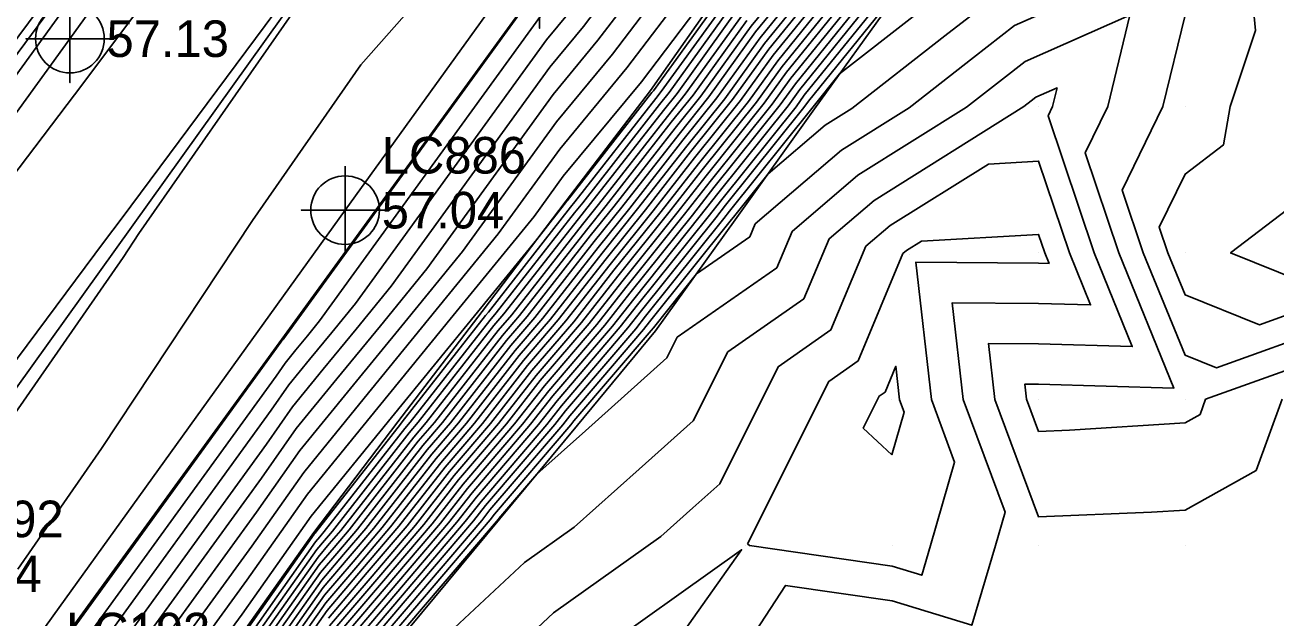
# Model space of a CAD drawing. Extents: x 2188792 to 2191981, y 386090 to 389710.
# Drawn here: x 2190090.9 to 2190176.3, y 387535.2 to 387575.7 of the extents above; entities that cross this region are included whole.
import ezdxf

# ---------------------------------------------------------------- set-up
doc = ezdxf.new("R2010")
doc.units = 0
for name, color, linetype in [('DTM Contours Major', 7, 'Continuous'), ('DTM Contours Minor', 7, 'Continuous'), ('Exist DTM Breakline', 7, 'Continuous'), ('Exist DTM QL2 LIDAR Elevation Point', 7, 'Continuous'), ('Exist Roads EOP', 7, 'Continuous'), ('Exist Roads EOP Cogo Number', 7, 'Continuous'), ('Exist Roads EOP Cogo Point CELL', 7, 'Continuous'), ('Exist Roads EOT', 7, 'Continuous'), ('Exist Roads EOT Cogo Elevation', 7, 'Continuous'), ('Exist Roads EOT Cogo Number', 7, 'Continuous'), ('Exist Roads EOT Cogo Point CELL', 7, 'Continuous'), ('PH Exist DTM Breakline', 7, 'Continuous')]:
    doc.layers.add(name, color=color, linetype=linetype)

msp = doc.modelspace()

# ---------------------------------------------------------------- linework, layer by layer
at = {"layer": 'DTM Contours Major'}
for points in [[(2190151.311, 387661.898), (2190146.496, 387654.704), (2190134.166, 387637.26), (2190130.399, 387632.051), (2190120.729, 387617.824), (2190106.225, 387596.486), (2190103.722, 387593.114), (2190101.482, 387589.813), (2190086.86, 387570.121)], [(2190091.393, 387530.607), (2190108.388, 387554.062), (2190108.431, 387554.123), (2190108.48, 387554.184), (2190108.533, 387554.249), (2190108.59, 387554.318), (2190126.056, 387578.434), (2190126.083, 387578.467), (2190126.108, 387578.499), (2190126.134, 387578.534), (2190140.156, 387597.174), (2190140.433, 387597.539), (2190140.728, 387597.929), (2190141.045, 387598.361), (2190157.562, 387620.323), (2190158.167, 387621.152), (2190158.815, 387622.039), (2190167.49, 387633.85), (2190168.237, 387634.874), (2190169.128, 387635.987), (2190170.079, 387637.175), (2190184.662, 387656.987)], [(2190177.393, 387635.531), (2190172.172, 387629.008), (2190167.794, 387623.009), (2190166.39, 387621.099), (2190162.031, 387615.129), (2190157.956, 387609.549), (2190154.257, 387604.63), (2190150.045, 387598.88), (2190146.112, 387593.69), (2190142.422, 387588.822), (2190138.204, 387583.214), (2190134.502, 387578.326), (2190131.026, 387573.736), (2190127.204, 387569.116), (2190120.791, 387560.26), (2190116.838, 387555.416), (2190113.147, 387550.892), (2190109.69, 387546.656), (2190106.731, 387542.448), (2190099.469, 387532.426)], [(2190169.273, 387580.455), (2190158.49, 387575.684), (2190155.69, 387573.497), (2190151.295, 387570.066), (2190146.666, 387567.17), (2190140.766, 387562.135), (2190140.401, 387561.263), (2190136.765, 387558.722), (2190133.821, 387555.045), (2190133.672, 387554.855), (2190128.4, 387548.688), (2190128.178, 387548.404), (2190122.969, 387542.303), (2190122.673, 387541.925), (2190117.527, 387535.891), (2190112.507, 387530.004)], [(2190143.014, 387577.991), (2190140.804, 387575.248), (2190137.609, 387570.809), (2190135.571, 387568.267), (2190131.668, 387563.281), (2190129.782, 387560.925), (2190125.733, 387555.752), (2190124.086, 387553.825), (2190119.96, 387548.549), (2190118.379, 387546.697), (2190114.177, 387541.317), (2190112.663, 387539.541), (2190111.185, 387537.809), (2190107.45, 387532.511)], [(2190139.296, 387577.214), (2190134.904, 387571.112), (2190134.247, 387570.293), (2190128.993, 387563.582), (2190128.436, 387562.886), (2190123.087, 387556.051), (2190122.648, 387555.538), (2190117.221, 387548.597), (2190116.85, 387548.162), (2190111.345, 387541.114), (2190111.041, 387540.758), (2190110.745, 387540.41), (2190105.891, 387533.526)], [(2190145.974, 387577.826), (2190142.312, 387573.281), (2190140.314, 387570.505), (2190136.896, 387566.242), (2190134.342, 387562.979), (2190131.128, 387558.965), (2190128.38, 387555.453), (2190125.524, 387552.113), (2190122.7, 387548.5), (2190119.909, 387545.232), (2190117.009, 387541.519), (2190114.284, 387538.324), (2190111.626, 387535.207)], [(2190148.934, 387577.661), (2190143.82, 387571.315), (2190143.019, 387570.201), (2190138.221, 387564.216), (2190137.017, 387562.678), (2190132.475, 387557.005), (2190131.026, 387555.154), (2190126.962, 387550.4), (2190125.439, 387548.452), (2190121.439, 387543.768), (2190119.841, 387541.722), (2190115.906, 387537.107), (2190112.067, 387532.606)], [(2190180.125, 387555.127), (2190172.269, 387552.302), (2190170.124, 387553.171), (2190167.274, 387560.158), (2190165.833, 387564.449), (2190168.607, 387570.159), (2190170.124, 387576.403)], [(2190150.107, 387546.353), (2190150.948, 387549.282), (2190150.634, 387550.129), (2190150.378, 387552.411), (2190149.642, 387550.652), (2190149.246, 387550.376), (2190148.148, 387548.178), (2190150.107, 387546.353)]]:
    msp.add_lwpolyline(points, dxfattribs=at)
at = {"layer": 'DTM Contours Minor'}
for points in [[(2190065.514, 387514.559), (2190081.303, 387536.264), (2190082.63, 387538.282), (2190097.61, 387559.851), (2190098.692, 387561.489), (2190115.183, 387585.188), (2190115.572, 387585.629), (2190129.097, 387601.222), (2190133.281, 387605.947), (2190145.736, 387620.245), (2190151.288, 387627.466), (2190156.609, 387634.62), (2190165.07, 387645.609), (2190174.107, 387657.741), (2190181.981, 387667.906), (2190187.788, 387675.299), (2190199.057, 387689.861), (2190205.414, 387697.968), (2190216.141, 387711.606), (2190219.575, 387716.076), (2190234.549, 387735.079)], [(2190084.006, 387557.4), (2190094.856, 387571.695), (2190099.134, 387577.453), (2190107.444, 387593.46), (2190110.09, 387597.703), (2190119.651, 387612.941), (2190119.659, 387612.954), (2190119.678, 387612.982), (2190128.004, 387625.475), (2190135.398, 387636.642), (2190136.43, 387638.136), (2190139.311, 387642.336), (2190151.615, 387659.742)], [(2190184.837, 387659.663), (2190167.502, 387636.111), (2190167.475, 387636.078), (2190167.45, 387636.047), (2190167.429, 387636.018), (2190165.598, 387633.525), (2190156.429, 387623.349), (2190154.429, 387620.887), (2190143.422, 387606.569), (2190142.383, 387605.376), (2190126.829, 387587.81), (2190122.267, 387582.551), (2190113.856, 387573.015), (2190106.443, 387562.363), (2190096.147, 387546.786), (2190090.433, 387538.558)], [(2190094.623, 387531.335), (2190107.725, 387549.417), (2190108.935, 387551.136), (2190110.347, 387552.867), (2190111.855, 387554.716), (2190113.47, 387556.695), (2190126.515, 387574.707), (2190128.06, 387576.575), (2190129.465, 387578.43), (2190130.962, 387580.406), (2190141.062, 387593.833), (2190142.704, 387596), (2190144.455, 387598.31), (2190146.33, 387600.869), (2190157.72, 387616.014), (2190159.713, 387618.743), (2190161.845, 387621.663), (2190167.611, 387629.514), (2190169.811, 387632.527), (2190172.434, 387635.805), (2190175.234, 387639.303), (2190184.312, 387651.637), (2190187.135, 387655.131), (2190190.153, 387658.866)], [(2190096.239, 387531.699), (2190107.394, 387547.094), (2190109.187, 387549.643), (2190111.28, 387552.209), (2190113.516, 387554.949), (2190115.911, 387557.883), (2190126.745, 387572.843), (2190129.049, 387575.628), (2190131.144, 387578.395), (2190133.376, 387581.342), (2190141.516, 387592.162), (2190143.84, 387595.23), (2190146.318, 387598.5), (2190148.972, 387602.122), (2190157.799, 387613.859), (2190160.485, 387617.538), (2190163.36, 387621.475), (2190167.672, 387627.346), (2190170.598, 387631.354), (2190174.087, 387635.713), (2190177.811, 387640.367), (2190184.137, 387648.961), (2190187.814, 387653.513), (2190191.746, 387658.38)], [(2190155.266, 387658.13), (2190146.358, 387642.623), (2190143.945, 387639.083), (2190134.669, 387623.313), (2190128.018, 387610.831), (2190124.584, 387604.112), (2190115.056, 387586.462), (2190114.502, 387585.393), (2190097.474, 387562.47), (2190096.333, 387560.967), (2190081.138, 387540.528)], [(2190193.339, 387657.893), (2190188.494, 387651.895), (2190183.962, 387646.286), (2190180.388, 387641.431), (2190175.74, 387635.622), (2190171.385, 387630.181), (2190167.733, 387625.177), (2190164.875, 387621.287), (2190161.258, 387616.333), (2190157.877, 387611.704), (2190151.614, 387603.376), (2190148.181, 387598.69), (2190144.976, 387594.46), (2190141.969, 387590.492), (2190135.79, 387582.278), (2190132.823, 387578.36), (2190130.037, 387574.682), (2190126.975, 387570.98), (2190118.351, 387559.072), (2190115.177, 387555.183), (2190112.213, 387551.55), (2190109.438, 387548.149), (2190107.063, 387544.771), (2190097.854, 387532.062)], [(2190093.008, 387530.971), (2190108.057, 387551.739), (2190108.683, 387552.629), (2190109.414, 387553.525), (2190110.194, 387554.482), (2190111.03, 387555.507), (2190126.286, 387576.571), (2190127.072, 387577.521), (2190127.786, 387578.465), (2190128.548, 387579.47), (2190140.609, 387595.503), (2190141.569, 387596.769), (2190142.592, 387598.119), (2190143.687, 387599.615), (2190157.641, 387618.168), (2190158.94, 387619.948), (2190160.33, 387621.851), (2190167.551, 387631.682), (2190169.024, 387633.701), (2190170.781, 387635.896), (2190172.656, 387638.239), (2190184.487, 387654.312), (2190186.455, 387656.748)], [(2190178.377, 387635.321), (2190172.918, 387628.192), (2190172.819, 387628.073), (2190167.873, 387620.922), (2190167.864, 387620.912), (2190167.856, 387620.899), (2190167.133, 387619.852), (2190162.804, 387613.924), (2190158.035, 387607.394), (2190156.899, 387605.883), (2190151.908, 387599.07), (2190147.247, 387592.92), (2190142.876, 387587.151), (2190140.618, 387584.151), (2190136.181, 387578.291), (2190132.014, 387572.79), (2190127.434, 387567.252), (2190123.231, 387561.449), (2190118.499, 387555.65), (2190114.08, 387550.234), (2190109.942, 387545.163), (2190106.4, 387540.126), (2190101.085, 387532.79)], [(2190179.645, 387600.268), (2190166.841, 387600.381), (2190164.196, 387595.683), (2190161.55, 387590.985), (2190161.433, 387588.872), (2190158.752, 387584.11), (2190156.319, 387583.034), (2190151.417, 387579.207), (2190150.177, 387577.677), (2190150.118, 387577.594), (2190144.424, 387570.528), (2190144.101, 387570.08), (2190138.751, 387563.406), (2190138.087, 387562.558), (2190133.013, 387556.221), (2190132.085, 387555.034), (2190127.537, 387549.715), (2190126.535, 387548.433), (2190122.051, 387543.182), (2190120.974, 387541.803), (2190116.554, 387536.621), (2190112.243, 387531.565)], [(2190176.91, 387596.947), (2190167.918, 387597.026), (2190166.141, 387593.87), (2190164.364, 387590.714), (2190164.113, 387586.185), (2190162.259, 387582.892), (2190157.043, 387580.584), (2190151.758, 387576.458), (2190146.533, 387572.379), (2190144.725, 387570.135), (2190144.642, 387570.019), (2190139.016, 387563.001), (2190138.622, 387562.497), (2190133.282, 387555.829), (2190132.614, 387554.974), (2190127.825, 387549.373), (2190127.082, 387548.423), (2190122.357, 387542.889), (2190121.541, 387541.844), (2190116.879, 387536.377), (2190112.331, 387531.045)], [(2190180.125, 387557.007), (2190175.203, 387555.237), (2190170.124, 387557.294), (2190168.956, 387560.158), (2190168.365, 387561.917), (2190170.124, 387565.536), (2190172.749, 387567.533), (2190173.213, 387570.159), (2190174.944, 387575.34), (2190174.477, 387580.16)], [(2190137.859, 387578.256), (2190133.003, 387571.844), (2190127.664, 387565.389), (2190125.671, 387562.637), (2190120.16, 387555.884), (2190115.013, 387549.575), (2190110.194, 387543.67), (2190106.069, 387537.803), (2190102.7, 387533.154)], [(2190138.692, 387578.001), (2190133.822, 387571.234), (2190133.717, 387571.103), (2190127.923, 387563.702), (2190127.897, 387563.67), (2190125.86, 387561.066), (2190121.821, 387556.117), (2190115.946, 387548.917), (2190110.446, 387542.176), (2190105.738, 387535.48), (2190104.315, 387533.517)], [(2190142.422, 387578.024), (2190140.502, 387575.641), (2190137.068, 387570.869), (2190135.306, 387568.672), (2190131.133, 387563.341), (2190129.513, 387561.317), (2190125.204, 387555.812), (2190123.798, 387554.168), (2190119.412, 387548.558), (2190118.073, 387546.99), (2190113.611, 387541.276), (2190112.338, 387539.784), (2190111.097, 387538.329), (2190107.139, 387532.714)], [(2190143.606, 387577.958), (2190141.105, 387574.855), (2190138.15, 387570.748), (2190135.836, 387567.862), (2190132.203, 387563.22), (2190130.051, 387560.533), (2190126.263, 387555.692), (2190124.373, 387553.483), (2190120.508, 387548.539), (2190118.685, 387546.404), (2190114.743, 387541.357), (2190112.987, 387539.298), (2190111.274, 387537.288), (2190107.762, 387532.308)], [(2190157.767, 387578.134), (2190153.724, 387574.977), (2190147.38, 387570.025), (2190145.555, 387568.882), (2190141.649, 387565.55), (2190139.281, 387562.596), (2190139.157, 387562.437), (2190133.552, 387555.437), (2190133.143, 387554.915), (2190128.112, 387549.03), (2190127.63, 387548.414), (2190122.663, 387542.596), (2190122.107, 387541.884), (2190117.203, 387536.134), (2190112.419, 387530.525)], [(2190138.994, 387577.608), (2190134.363, 387571.173), (2190133.982, 387570.698), (2190128.458, 387563.642), (2190128.166, 387563.278), (2190122.558, 387556.111), (2190122.36, 387555.88), (2190116.673, 387548.606), (2190116.544, 387548.455), (2190110.778, 387541.073), (2190110.717, 387541.001), (2190110.657, 387540.931), (2190105.579, 387533.729)], [(2190144.198, 387577.925), (2190141.407, 387574.461), (2190138.691, 387570.687), (2190136.101, 387567.457), (2190132.738, 387563.16), (2190130.321, 387560.141), (2190126.792, 387555.632), (2190124.661, 387553.14), (2190121.056, 387548.529), (2190118.991, 387546.111), (2190115.31, 387541.398), (2190113.311, 387539.054), (2190111.362, 387536.768), (2190108.074, 387532.105)], [(2190144.79, 387577.892), (2190141.709, 387574.068), (2190139.232, 387570.626), (2190136.366, 387567.052), (2190133.273, 387563.1), (2190130.59, 387559.749), (2190127.321, 387555.573), (2190124.949, 387552.798), (2190121.604, 387548.52), (2190119.297, 387545.818), (2190115.876, 387541.438), (2190113.636, 387538.811), (2190111.45, 387536.248), (2190108.386, 387531.902)], [(2190145.382, 387577.859), (2190142.01, 387573.675), (2190139.773, 387570.566), (2190136.631, 387566.647), (2190133.807, 387563.04), (2190130.859, 387559.357), (2190127.85, 387555.513), (2190125.236, 387552.455), (2190122.152, 387548.51), (2190119.603, 387545.525), (2190116.443, 387541.479), (2190113.96, 387538.568), (2190111.538, 387535.728), (2190108.698, 387531.699)], [(2190146.566, 387577.793), (2190142.614, 387572.888), (2190140.855, 387570.444), (2190137.161, 387565.837), (2190134.877, 387562.919), (2190131.398, 387558.573), (2190128.909, 387555.393), (2190125.812, 387551.77), (2190123.247, 387548.491), (2190120.215, 387544.94), (2190117.576, 387541.56), (2190114.608, 387538.081), (2190111.714, 387534.687)], [(2190147.158, 387577.76), (2190142.915, 387572.495), (2190141.396, 387570.384), (2190137.426, 387565.431), (2190135.412, 387562.859), (2190131.667, 387558.181), (2190129.438, 387555.333), (2190126.099, 387551.428), (2190123.795, 387548.481), (2190120.521, 387544.647), (2190118.142, 387541.601), (2190114.933, 387537.837), (2190111.802, 387534.167)], [(2190147.75, 387577.727), (2190143.217, 387572.102), (2190141.937, 387570.323), (2190137.691, 387565.026), (2190135.947, 387562.799), (2190131.936, 387557.789), (2190129.967, 387555.274), (2190126.387, 387551.085), (2190124.343, 387548.471), (2190120.827, 387544.354), (2190118.708, 387541.641), (2190115.257, 387537.594), (2190111.89, 387533.646)], [(2190148.342, 387577.694), (2190143.519, 387571.708), (2190142.478, 387570.262), (2190137.956, 387564.621), (2190136.482, 387562.738), (2190132.205, 387557.397), (2190130.497, 387555.214), (2190126.674, 387550.743), (2190124.891, 387548.462), (2190121.133, 387544.061), (2190119.275, 387541.682), (2190115.581, 387537.351), (2190111.979, 387533.126)], [(2190149.526, 387577.627), (2190144.122, 387570.922), (2190143.56, 387570.141), (2190138.486, 387563.811), (2190137.552, 387562.618), (2190132.744, 387556.613), (2190131.555, 387555.094), (2190127.25, 387550.058), (2190125.987, 387548.443), (2190121.745, 387543.475), (2190120.408, 387541.763), (2190116.23, 387536.864), (2190112.155, 387532.085)], [(2190139.597, 387576.821), (2190135.445, 387571.052), (2190134.512, 387569.888), (2190129.528, 387563.522), (2190128.705, 387562.494), (2190123.616, 387555.991), (2190122.935, 387555.195), (2190117.769, 387548.587), (2190117.156, 387547.869), (2190111.911, 387541.154), (2190111.365, 387540.514), (2190110.833, 387539.89), (2190106.203, 387533.323)], [(2190139.899, 387576.428), (2190135.986, 387570.991), (2190134.777, 387569.483), (2190130.063, 387563.461), (2190128.974, 387562.102), (2190124.145, 387555.932), (2190123.223, 387554.853), (2190118.317, 387548.577), (2190117.462, 387547.576), (2190112.478, 387541.195), (2190111.69, 387540.271), (2190110.921, 387539.37), (2190106.515, 387533.12)], [(2190180.125, 387553.248), (2190171.529, 387550.157), (2190171.155, 387549.125), (2190170.124, 387548.551), (2190162.228, 387548.052), (2190160.123, 387547.964), (2190159.309, 387550.155), (2190159.192, 387551.198), (2190160.123, 387551.191), (2190169.36, 387550.921), (2190165.593, 387560.158), (2190163.301, 387566.981), (2190164.845, 387570.159), (2190166.359, 387576.395), (2190159.214, 387573.234), (2190157.656, 387572.017), (2190155.21, 387570.107), (2190147.777, 387565.457), (2190143.29, 387561.628), (2190142.249, 387559.141), (2190135.453, 387554.39), (2190134.747, 387552.979), (2190129.185, 387548.008), (2190125.856, 387545.033), (2190123.275, 387542.01), (2190123.24, 387541.966), (2190117.852, 387535.647), (2190112.595, 387529.484)], [(2190140.201, 387576.035), (2190136.527, 387570.93), (2190135.042, 387569.077), (2190130.598, 387563.401), (2190129.243, 387561.71), (2190124.675, 387555.872), (2190123.511, 387554.51), (2190118.865, 387548.568), (2190117.767, 387547.283), (2190113.044, 387541.236), (2190112.014, 387540.028), (2190111.009, 387538.849), (2190106.827, 387532.917)], [(2190176.754, 387550.157), (2190174.99, 387545.291), (2190170.124, 387542.582), (2190167.842, 387542.438), (2190160.123, 387542.115), (2190157.141, 387550.148), (2190156.711, 387553.973), (2190160.123, 387553.947), (2190166.52, 387553.76), (2190163.911, 387560.158), (2190160.768, 387569.513), (2190161.082, 387570.159), (2190161.39, 387571.426), (2190159.938, 387570.784), (2190159.621, 387570.536), (2190159.124, 387570.148), (2190148.889, 387563.745), (2190145.813, 387561.12), (2190144.097, 387557.019), (2190138.901, 387553.387), (2190136.548, 387548.681), (2190132.85, 387545.376), (2190128.423, 387541.419), (2190125.03, 387538.995), (2190120.233, 387534.548)], [(2190124.077, 387532.84), (2190127.009, 387535.558), (2190134.32, 387540.782), (2190136.516, 387542.744), (2190138.349, 387544.383), (2190142.35, 387552.383), (2190145.945, 387554.897), (2190148.337, 387560.613), (2190150, 387562.032), (2190156.707, 387566.228), (2190160.123, 387566.429), (2190162.229, 387560.158), (2190163.68, 387556.6), (2190160.123, 387556.704), (2190154.23, 387556.748), (2190154.972, 387550.142), (2190157.833, 387542.433), (2190157.179, 387540.156), (2190155.555, 387534.723), (2190150.122, 387536.394), (2190142.832, 387537.445), (2190140.121, 387533.244)], [(2190178.138, 387558.171), (2190173.233, 387560.158), (2190177.147, 387563.135)], [(2190140.251, 387540.286), (2190145.798, 387551.379), (2190147.794, 387552.774), (2190150.861, 387560.106), (2190151.112, 387560.319), (2190152.122, 387560.951), (2190160.123, 387561.424), (2190160.548, 387560.158), (2190160.841, 387559.44), (2190160.123, 387559.461), (2190151.749, 387559.523), (2190152.803, 387550.136), (2190154.391, 387545.858), (2190152.753, 387540.156), (2190152.148, 387538.13), (2190150.122, 387538.753), (2190140.391, 387540.156), (2190140.251, 387540.286)], [(2190137.419, 387512.855), (2190133.935, 387520.154), (2190131.456, 387528.819), (2190132.964, 387530.155), (2190139.84, 387539.876), (2190128.988, 387532.121), (2190127.921, 387531.132), (2190119.493, 387524.101), (2190117.957, 387522.653), (2190117.61, 387520.473), (2190117.263, 387519.247), (2190119.789, 387513.362), (2190122.207, 387517.975), (2190130.12, 387516.003), (2190137.419, 387512.855)]]:
    msp.add_lwpolyline(points, dxfattribs=at)
at = {"layer": 'Exist DTM Breakline'}
msp.add_lwpolyline([(2189998.889, 387447.645), (2190035.636, 387497.082), (2190069.466, 387545.534), (2190104.367, 387592.678), (2190135.108, 387636.538), (2190168.392, 387682.449), (2190194.386, 387718.656)], dxfattribs=at)
at = {"layer": 'Exist DTM QL2 LIDAR Elevation Point'}
for p, q in [((2190160.123, 387570.159), (2190160.123, 387570.159)), ((2190170.124, 387570.159), (2190170.124, 387570.159)), ((2190151.309, 387560.016), (2190151.309, 387560.016)), ((2190160.123, 387560.158), (2190160.123, 387560.158)), ((2190170.124, 387560.158), (2190170.124, 387560.158)), ((2190150.098, 387550.128), (2190150.098, 387550.128)), ((2190160.123, 387550.157), (2190160.123, 387550.157)), ((2190170.124, 387550.157), (2190170.124, 387550.157)), ((2190140.121, 387540.156), (2190140.121, 387540.156)), ((2190150.122, 387540.156), (2190150.122, 387540.156)), ((2190160.123, 387540.156), (2190160.123, 387540.156)), ((2190170.124, 387540.156), (2190170.124, 387540.156))]:
    msp.add_line(p, q, dxfattribs=at)
at = {"layer": 'Exist Roads EOP'}
for points in [[(2190313.986, 387884.141), (2190285.547, 387843.636), (2190254.588, 387800.045), (2190225.155, 387759.32), (2190194.829, 387717.425), (2190164.291, 387675.101), (2190137.229, 387637.301), (2190105.098, 387592.774), (2190071.411, 387546.221), (2190039.296, 387501.568), (2190007.542, 387457.958), (2189976.844, 387415.407), (2189936.359, 387359.145), (2189907.138, 387318.716), (2189868.636, 387265.243), (2189836.428, 387220.463), (2189805.695, 387177.815), (2189775.592, 387135.957), (2189745.498, 387094.055), (2189715.496, 387052.249), (2189683.869, 387008.07), (2189653.218, 386965.867), (2189623.729, 386924.667)], [(2190335.128, 387868.989), (2190306.373, 387829.271), (2190274.581, 387784.921), (2190245.133, 387744.071), (2190214.553, 387701.741), (2190184.89, 387660.475), (2190157.493, 387622.204), (2190126.048, 387578.501), (2190091.216, 387530.568), (2190059.634, 387486.726), (2190026.932, 387441.783), (2189997.689, 387401.032), (2189957.023, 387344.154), (2189927.908, 387303.922), (2189889.008, 387250.224), (2189856.606, 387205.5), (2189825.68, 387162.612), (2189795.668, 387120.822), (2189765.955, 387079.619), (2189734.998, 387036.704), (2189703.849, 386993.356), (2189673.984, 386951.979), (2189643.253, 386909.427)]]:
    msp.add_lwpolyline(points, dxfattribs=at)
at = {"layer": 'Exist Roads EOP Cogo Point CELL'}
msp.add_lwpolyline([(2190126.048, 387581.501), (2190126.048, 387575.501), (2190126.048, 387578.501), (2190129.048, 387578.501), (2190123.048, 387578.501)], dxfattribs=at)
at = {"layer": 'Exist Roads EOT'}
for points in [[(2189910.407, 387320.236), (2189942.075, 387364.22), (2189970.438, 387403.768), (2190000.916, 387446.161), (2190032.053, 387489.248), (2190063.107, 387532.142), (2190093.978, 387574.79), (2190125.104, 387617.946), (2190155.102, 387659.638), (2190185.949, 387702.484), (2190216.886, 387745.11), (2190247.602, 387787.3), (2190276.876, 387828.015), (2190303.928, 387865.67), (2190323.039, 387892.195)], [(2190333.162, 387868.755), (2190301.785, 387825.12), (2190269.645, 387780.315), (2190237.827, 387736.49), (2190205.816, 387692.275), (2190173.845, 387647.822), (2190143.211, 387605.324), (2190112.772, 387563.076), (2190082.117, 387520.492), (2190050.947, 387477.405), (2190019.959, 387434.524), (2189989.253, 387391.986)], [(2190174.375, 387667.889), (2190147.471, 387630.495), (2190115.247, 387585.778), (2190081.202, 387538.232), (2190049.502, 387494.256), (2190017.538, 387450.182), (2189987.334, 387408.357), (2189946.666, 387352.019), (2189917.402, 387311.129), (2189878.955, 387257.772), (2189846.565, 387212.819), (2189815.837, 387170.306), (2189785.374, 387128.351), (2189755.717, 387086.921), (2189724.953, 387044.041), (2189693.727, 387000.805), (2189663.933, 386959.217), (2189633.425, 386917.196)]]:
    msp.add_lwpolyline(points, dxfattribs=at)
at = {"layer": 'Exist Roads EOT Cogo Point CELL'}
for points in [[(2190093.978, 387577.79), (2190093.978, 387571.79), (2190093.978, 387574.79), (2190090.978, 387574.79), (2190096.978, 387574.79)], [(2190112.772, 387566.076), (2190112.772, 387560.076), (2190112.772, 387563.076), (2190109.772, 387563.076), (2190115.772, 387563.076)]]:
    msp.add_lwpolyline(points, dxfattribs=at)
for centre in [(2190093.978, 387574.79), (2190112.772, 387563.076)]:
    msp.add_circle(centre, 2.344, dxfattribs=at)
at = {"layer": 'PH Exist DTM Breakline'}
for points in [[(2190172.743, 387628.156), (2190167.852, 387620.917), (2190162.961, 387613.678), (2190158.07, 387606.439), (2190153.179, 387599.2), (2190148.288, 387592.214), (2190143.398, 387585.228), (2190138.507, 387578.243), (2190133.616, 387571.257), (2190127.871, 387563.708), (2190122.125, 387556.16), (2190116.38, 387548.611), (2190110.634, 387541.063), (2190105.495, 387533.783), (2190100.357, 387526.504), (2190095.218, 387519.224)], [(2190102.826, 387514.545), (2190106.944, 387521.936), (2190112.657, 387529.121), (2190117.986, 387535.546), (2190123.316, 387541.971), (2190128.645, 387548.396), (2190133.975, 387554.821), (2190139.403, 387562.409), (2190144.831, 387569.998), (2190150.258, 387577.587), (2190155.686, 387585.175), (2190159.091, 387591.221), (2190162.495, 387597.267), (2190165.899, 387603.313), (2190169.9, 387611.225), (2190173.713, 387618.372), (2190177.189, 387623.277)]]:
    msp.add_lwpolyline(points, dxfattribs=at)

# ---------------------------------------------------------------- texts
at = {"layer": 'Exist Roads EOP Cogo Number'}
msp.add_text('LC193', height=2.5, dxfattribs=at).set_placement((2190093.716, 387533.068))
at = {"layer": 'Exist Roads EOT Cogo Elevation'}
for s, p in [('57.13', (2190096.478, 387573.54)), ('57.04', (2190115.272, 387561.826)), ('57.44', (2190083.702, 387536.982))]:
    msp.add_text(s, height=2.5, dxfattribs=at).set_placement(p)
at = {"layer": 'Exist Roads EOT Cogo Number'}
for s, p in [('LC886', (2190115.272, 387565.576)), ('LC192', (2190083.702, 387540.732))]:
    msp.add_text(s, height=2.5, dxfattribs=at).set_placement(p)

doc.saveas('drawing.dxf')
